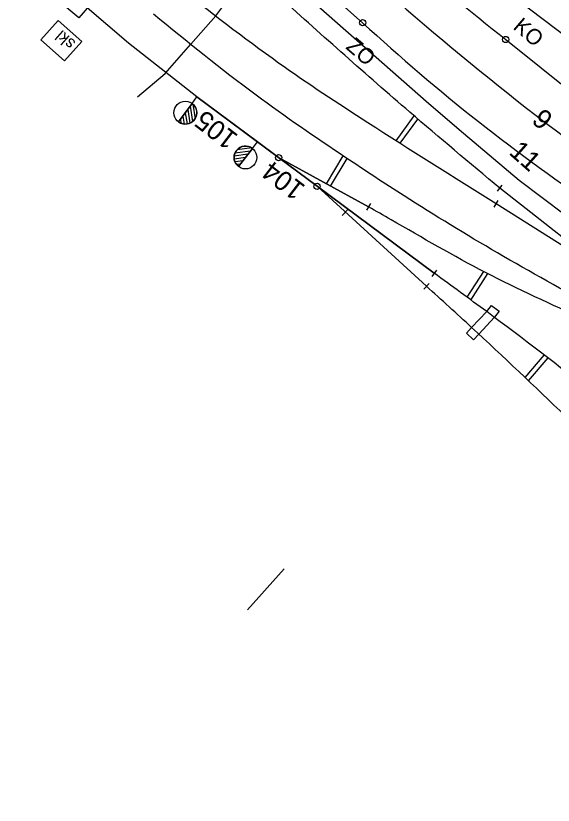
# Model space of a CAD drawing. Extents: x -496570 to -495506, y -1089156 to -1088046.
# Drawn here: x -496138 to -496069.2, y -1088643 to -1088542 of the extents above; entities that cross this region are included whole.
import ezdxf

# ---------------------------------------------------------------- set-up
doc = ezdxf.new("R2010")
doc.units = 0
for name, color, linetype in [('11', 7, 'Continuous'), ('14', 7, 'Continuous'), ('27', 7, 'Continuous'), ('39', 7, 'Continuous'), ('49', 7, 'Continuous'), ('54', 7, 'Continuous'), ('PŮVODNÍ_NÁVRH', 7, 'Continuous')]:
    doc.layers.add(name, color=color, linetype=linetype)

msp = doc.modelspace()

# ---------------------------------------------------------------- linework, layer by layer
at = {"layer": '11'}
for p, q in [((-496089.329, -1088557.949), (-496087.015, -1088554.79)), ((-496088.821, -1088558.27), (-496086.559, -1088555.183)), ((-496098.233, -1088563.473), (-496096.091, -1088559.905)), ((-496097.706, -1088563.762), (-496095.591, -1088560.24)), ((-496080.245, -1088577.995), (-496078.134, -1088574.703)), ((-496079.76, -1088578.35), (-496077.588, -1088574.963)), ((-496072.825, -1088588.251), (-496070.379, -1088585.388)), ((-496072.39, -1088588.665), (-496069.905, -1088585.757))]:
    msp.add_line(p, q, dxfattribs=at)
at = {"layer": '14'}
msp.add_line((-496075.335, -1088538.747), (-496053.911, -1088555.054), dxfattribs=at)
for points in [[(-496093.621, -1088542.853), (-496114.06, -1088524.717), (-496138.8, -1088502.766), (-496174.593, -1088471.013)], [(-496084.463, -1088574.911), (-496099.443, -1088563.786), (-496104.369, -1088560.115), (-496107.079, -1088558.115), (-496114.808, -1088552.356), (-496123.542, -1088545.463), (-496128.839, -1088540.929), (-496131.495, -1088538.579)], [(-496075.31, -1088545), (-496052.489, -1088563.281), (-496031.561, -1088580.038)], [(-496092.861, -1088566.414), (-496104.369, -1088560.115)], [(-496085.454, -1088576.574), (-496099.443, -1088563.786)], [(-496061.169, -1088575.721), (-496076.075, -1088564.025)], [(-496035.857, -1088592.043), (-496044.874, -1088586.073), (-496053.125, -1088580.797), (-496061.169, -1088575.721), (-496076.529, -1088566.028)]]:
    msp.add_lwpolyline(points, dxfattribs=at)
for centre in [(-496093.621, -1088542.853), (-496075.31, -1088545)]:
    msp.add_circle(centre, 0.4, dxfattribs=at)
for centre, major_axis, ratio, start_param, end_param in [((-495661.207, -1088025.176), (-508.889, 430.705), 0.9968688, 1.5476625, 1.6004047), ((-495832.376, -1088245.472), (-305.585, 244.796), 0.9982658, 1.5136379, 1.6390336), ((-495921.531, -1088356.146), (-198.567, 158.721), 0.9988584, 1.5005291, 1.6539577)]:
    msp.add_ellipse(centre, major_axis=major_axis, ratio=ratio, start_param=start_param, end_param=end_param, dxfattribs=at)
for points in [[(-496076.529, -1088566.028), (-496092.943, -1088555.668), (-496104.359, -1088548.012), (-496117.617, -1088537.987)], [(-496076.075, -1088564.025), (-496087.586, -1088554.298), (-496104.138, -1088539.66)], [(-496063.641, -1088579.453), (-496076.368, -1088572.308), (-496088.307, -1088565.016), (-496095.758, -1088560.128), (-496107.252, -1088552.116), (-496120.36, -1088541.773)], [(-496065.173, -1088580.858), (-496077.902, -1088574.814), (-496089.968, -1088568.076), (-496092.861, -1088566.414)], [(-496009.526, -1088642.986), (-496015.368, -1088636.526), (-496021.579, -1088629.917), (-496040.398, -1088611.545), (-496052.231, -1088600.497), (-496064.07, -1088590.377), (-496077.737, -1088579.829), (-496084.463, -1088574.911)], [(-496055.593, -1088604.743), (-496067.647, -1088593.203), (-496079.673, -1088581.848), (-496085.454, -1088576.574)]]:
    msp.add_spline(points, degree=3, dxfattribs=at)
at = {"layer": '27'}
for p, q in [((-496115.418, -1088553.184), (-496114.808, -1088552.356)), ((-496115.419, -1088553.184), (-496117.146, -1088555.546)), ((-496117.146, -1088555.546), (-496115.417, -1088553.185)), ((-496115.417, -1088553.185), (-496115.419, -1088553.184)), ((-496115.332, -1088553.258), (-496115.041, -1088555.134)), ((-496116.295, -1088554.385), (-496116.075, -1088555.811)), ((-496115.982, -1088553.955), (-496115.711, -1088555.71)), ((-496115.67, -1088553.528), (-496115.364, -1088555.502)), ((-496116.922, -1088555.241), (-496116.85, -1088555.711)), ((-496116.608, -1088554.812), (-496116.453, -1088555.815)), ((-496107.703, -1088558.932), (-496107.079, -1088558.115)), ((-496107.962, -1088559.27), (-496109.944, -1088559.53)), ((-496107.798, -1088558.871), (-496109.68, -1088559.117)), ((-496109.487, -1088561.253), (-496107.704, -1088558.932)), ((-496107.703, -1088558.933), (-496109.487, -1088561.253)), ((-496107.704, -1088558.932), (-496107.703, -1088558.933)), ((-496108.285, -1088559.69), (-496110.046, -1088559.921)), ((-496108.61, -1088560.111), (-496110.041, -1088560.298)), ((-496108.932, -1088560.531), (-496109.939, -1088560.663)), ((-496109.256, -1088560.952), (-496109.728, -1088561.015)), ((-496076.384, -1088564.418), (-496075.766, -1088563.632)), ((-496092.621, -1088565.975), (-496093.101, -1088566.853)), ((-496076.796, -1088566.451), (-496076.262, -1088565.605)), ((-496095.548, -1088566.793), (-496096.222, -1088567.531)), ((-496084.165, -1088574.51), (-496084.761, -1088575.312)), ((-496085.117, -1088576.205), (-496085.791, -1088576.943))]:
    msp.add_line(p, q, dxfattribs=at)
for points in [[(-496114.808, -1088552.356), (-496104.369, -1088560.115), (-496099.443, -1088563.786), (-496084.463, -1088574.911)], [(-496104.369, -1088560.115), (-496092.861, -1088566.414)], [(-496099.443, -1088563.786), (-496085.454, -1088576.574)], [(-496061.169, -1088575.721), (-496076.075, -1088564.025)], [(-496053.125, -1088580.797), (-496061.169, -1088575.721), (-496076.529, -1088566.028)]]:
    msp.add_lwpolyline(points, dxfattribs=at)
for centre, radius in [((-496116.286, -1088554.373), 1.462), ((-496108.601, -1088560.099), 1.462), ((-496104.369, -1088560.115), 0.4), ((-496099.443, -1088563.786), 0.4)]:
    msp.add_circle(centre, radius, dxfattribs=at)
for centre, start, end in [((-496116.282, -1088554.366), 233.81215, 53.773), ((-496108.595, -1088560.093), 52.49176, 232.45261)]:
    msp.add_arc(centre, 1.464, start, end, dxfattribs=at)
at = {"layer": '39'}
msp.add_line((-496108.33, -1088617.987), (-496103.641, -1088612.759), dxfattribs=at)
for points in [[(-496129.534, -1088545.247), (-496131.727, -1088547.738), (-496134.766, -1088545.053), (-496132.573, -1088542.562)], [(-496129.534, -1088545.247), (-496132.573, -1088542.562)]]:
    msp.add_lwpolyline(points, dxfattribs=at)
at = {"layer": '49'}
for points in [[(-496130.254, -1088537.45), (-496127.744, -1088539.662), (-496129.927, -1088542.223), (-496132.529, -1088540.032)], [(-496077.141, -1088579.026), (-496076.169, -1088579.748), (-496076.765, -1088580.551), (-496078.743, -1088582.69), (-496079.414, -1088583.431), (-496080.344, -1088582.589), (-496079.673, -1088581.848), (-496077.737, -1088579.829), (-496077.141, -1088579.026)]]:
    msp.add_lwpolyline(points, dxfattribs=at)
at = {"layer": '54'}
msp.add_lwpolyline([(-496165.07, -1088482.9), (-496156.87, -1088489.91), (-496145.17, -1088500.37), (-496132.17, -1088511.64), (-496132.14, -1088511.95), (-496109.93, -1088531.36), (-496085.16, -1088553.21), (-496080.73, -1088556.99), (-496073.59, -1088563.01), (-496067.7, -1088567.42), (-496060.271, -1088572.567), (-496056.99, -1088574.85), (-496054.978, -1088576.218), (-496044.9, -1088583.07), (-496037.32, -1088587.86), (-496035.7, -1088586.08), (-496034.22, -1088583.93), (-496031.57, -1088584.92), (-496029.17, -1088586.56)], dxfattribs=at)
at = {"layer": 'PŮVODNÍ_NÁVRH'}
msp.add_lwpolyline([(-496122.394, -1088552.331), (-496118.881, -1088549.335), (-496115.606, -1088545.612), (-496112.41, -1088541.972), (-496111.251, -1088540.429)], dxfattribs=at)

# ---------------------------------------------------------------- texts
at = {"layer": '14'}
for s, height, rotation, p in [('KO', 2, 319.41817, (-496074.491, -1088543.554)), ('ZO', 2, 319.41817, (-496095.88, -1088546.092)), ('9', 2.5, 318.48058, (-496072.134, -1088555.526)), ('11', 2.5, 318.48058, (-496075.021, -1088559.588))]:
    msp.add_text(s, height=height, rotation=rotation, dxfattribs=at).set_placement(p)
at = {"layer": '27'}
for s, rotation, p in [('105', 142.5143, (-496109.397, -1088557.3)), ('104', 142.47284, (-496100.799, -1088563.794))]:
    msp.add_text(s, height=2.5, rotation=rotation, dxfattribs=at).set_placement(p)
at = {"layer": '39'}
msp.add_text('skl', height=1.5, rotation=138.53894, dxfattribs=at).set_placement((-496130.242, -1088545.332))

doc.saveas('drawing.dxf')
